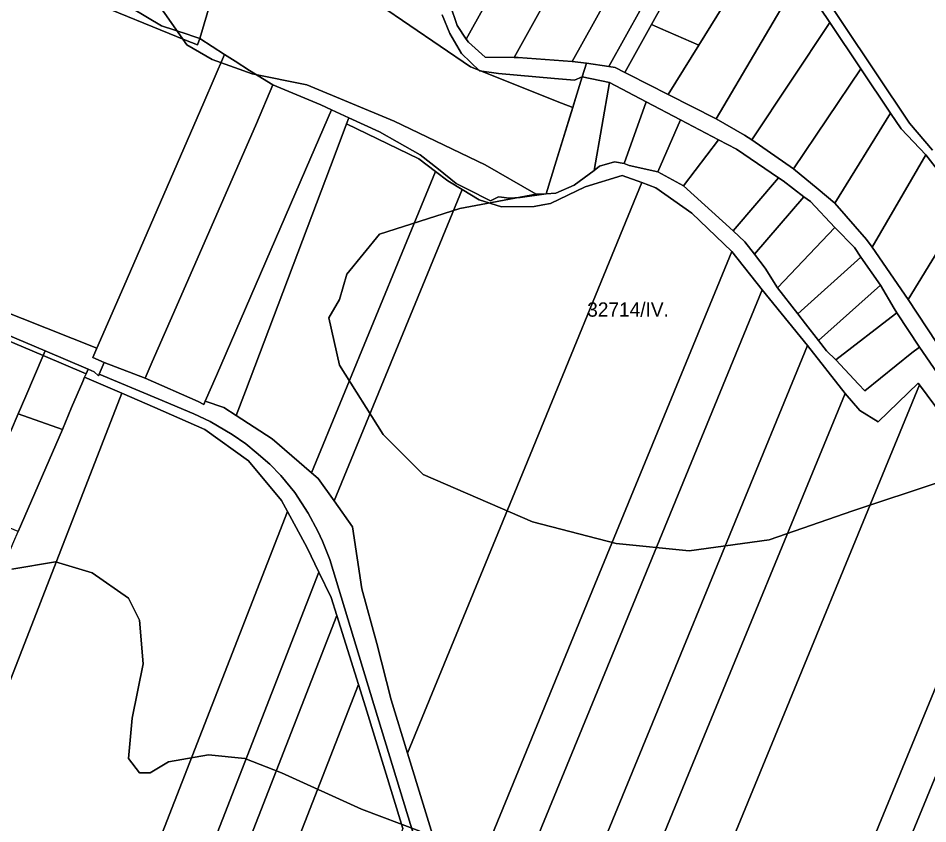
# Model space of a CAD drawing. Extents: x -545779 to -541342, y -1153413 to -1149956.
# Drawn here: x -543743 to -543424.2, y -1151725.6 to -1151443.3 of the extents above; entities that cross this region are included whole.
import ezdxf

# ---------------------------------------------------------------- set-up
doc = ezdxf.new("R2010")
doc.units = 0
for name, color, linetype in [('95560013', 7, 'Continuous'), ('95590013', 7, 'Continuous'), ('95600013', 7, 'Continuous'), ('95610013', 7, 'Continuous'), ('95620013', 7, 'Continuous'), ('95640013', 7, 'Continuous'), ('95660013', 7, 'Continuous')]:
    doc.layers.add(name, color=color, linetype=linetype)

msp = doc.modelspace()

# ---------------------------------------------------------------- linework, layer by layer
at = {"layer": '95560013'}
for points in [[(-543546.06, -1151342.91), (-543543.88, -1151346.35), (-543541.07, -1151350.8), (-543534.97, -1151358.76), (-543586.01, -1151450.59), (-543589.23, -1151445.86), (-543591.62, -1151438.6), (-543594.77, -1151430.54)], [(-543534.97, -1151358.76), (-543533.65, -1151360.47), (-543532.32, -1151361.53), (-543527.78, -1151365.16), (-543521.08, -1151368.18), (-543520.12, -1151368.63), (-543569.25, -1151457.02), (-543579.35, -1151456.9), (-543585.26, -1151451.7), (-543586.01, -1151450.59)], [(-543567.82, -1151457.04), (-543569.25, -1151457.02), (-543520.12, -1151368.63), (-543516.81, -1151370.19), (-543506.27, -1151375.14), (-543503.78, -1151376.31), (-543503.48, -1151376.77), (-543548.87, -1151458.44)], [(-543543.87, -1151459.07), (-543548.87, -1151458.44), (-543503.48, -1151376.77), (-543501.28, -1151380.06), (-543495.92, -1151388.1), (-543536.02, -1151460.25)], [(-543495.92, -1151388.1), (-543493.77, -1151391.33), (-543492.25, -1151393.62), (-543521.1, -1151445.52), (-543530.42, -1151462.28), (-543533.78, -1151460.57), (-543536.02, -1151460.25)], [(-543492.25, -1151393.62), (-543479.79, -1151412.85), (-543504.52, -1151452.78), (-543517.95, -1151446.9), (-543521.1, -1151445.52)], [(-543716.83, -1151562.15), (-543715.42, -1151558.92), (-543706.06, -1151537.35), (-543678.02, -1151472.79), (-543670.71, -1151455.96), (-543667, -1151458.37), (-543661.98, -1151461.63), (-543653.77, -1151466.67), (-543659.57, -1151480.23), (-543687.7, -1151544.6), (-543696.06, -1151563.74), (-543698.58, -1151569.5), (-543712.85, -1151563.9)], [(-543653.77, -1151466.67), (-543636.94, -1151473.63), (-543633.23, -1151475.34), (-543638.97, -1151488.6), (-543666.8, -1151552.84), (-543673.57, -1151568.46), (-543677.49, -1151577.51), (-543677.98, -1151578.64), (-543679.91, -1151577.65), (-543698.58, -1151569.5), (-543696.06, -1151563.74), (-543687.7, -1151544.6), (-543659.57, -1151480.23)], [(-543631.94, -1151490.93), (-543627.92, -1151480.3), (-543602.67, -1151492.57), (-543596.78, -1151496.97), (-543640.19, -1151602.62), (-543653.99, -1151590.76), (-543666.67, -1151582.48), (-543663.37, -1151574.05)], [(-543640.19, -1151602.62), (-543596.78, -1151496.97), (-543592.42, -1151500.23), (-543587.43, -1151503.28), (-543632.3, -1151612.47), (-543637.86, -1151604.63)], [(-543581.5, -1151506.9), (-543573.6, -1151509.37), (-543562.19, -1151509.28), (-543559.14, -1151508.73), (-543556.44, -1151508.25), (-543544.32, -1151502.42), (-543531.31, -1151498.38), (-543524.44, -1151500.91), (-543565.52, -1151600.89), (-543606.61, -1151700.87), (-543612.37, -1151682.17), (-543617.34, -1151662.42), (-543622.57, -1151643.32), (-543625.86, -1151621.57), (-543632.3, -1151612.47), (-543587.43, -1151503.28)], [(-543540.88, -1151641.8), (-543588.85, -1151758.53), (-543589.15, -1151757.56), (-543606.61, -1151700.87), (-543565.52, -1151600.89), (-543524.44, -1151500.91), (-543519.6, -1151502.7), (-543506.97, -1151511.62), (-543492.9, -1151525.06)], [(-543482.25, -1151538.53), (-543532.06, -1151659.72), (-543581.86, -1151780.91), (-543588.85, -1151758.53), (-543540.88, -1151641.8), (-543492.9, -1151525.06)], [(-543571.54, -1151813.98), (-543581.86, -1151780.91), (-543532.06, -1151659.72), (-543482.25, -1151538.53), (-543466.34, -1151558.01), (-543518.94, -1151685.99)], [(-543466.34, -1151558.01), (-543453.25, -1151574.82), (-543508.2, -1151708.53), (-543563.15, -1151842.24), (-543563.68, -1151840.49), (-543565.94, -1151831.89), (-543571.54, -1151813.98), (-543518.94, -1151685.99)], [(-543744.51, -1151626.74), (-543743.07, -1151623.2), (-543727.55, -1151587.41), (-543724.37, -1151579.78), (-543720.4, -1151570.58), (-543719.77, -1151569.13), (-543706.77, -1151574.74), (-543749.64, -1151684.78), (-543792.5, -1151794.83), (-543808.08, -1151778.88)], [(-543552.58, -1151876.88), (-543563.15, -1151842.24), (-543508.2, -1151708.53), (-543453.25, -1151574.82), (-543448.01, -1151580.83), (-543441.65, -1151584.81), (-543427.65, -1151571.22), (-543427.2, -1151571.8), (-543489.89, -1151724.34)], [(-543418.53, -1151627.26), (-543406.97, -1151642.49), (-543468.49, -1151792.18), (-543530.01, -1151941.87), (-543533.97, -1151930.97), (-543541.88, -1151911.96), (-543552.58, -1151876.88), (-543489.89, -1151724.34), (-543427.2, -1151571.8), (-543402.91, -1151604.4)], [(-543741.95, -1151855.55), (-543762.98, -1151828.24), (-543789.76, -1151797.63), (-543792.5, -1151794.83), (-543749.64, -1151684.78), (-543706.77, -1151574.74), (-543695.14, -1151579.76), (-543677.64, -1151587.49), (-543662.32, -1151598.44), (-543650.77, -1151612.28), (-543648.69, -1151616.13), (-543695.32, -1151735.84)], [(-543695.32, -1151735.84), (-543648.69, -1151616.13), (-543641.79, -1151628.89), (-543637.69, -1151637.4), (-543683.63, -1151755.34), (-543729.57, -1151873.29), (-543738.74, -1151859.72), (-543741.95, -1151855.55)], [(-543683.63, -1151755.34), (-543637.69, -1151637.4), (-543633.38, -1151646.34), (-543631.4, -1151652.63), (-543676.61, -1151768.7), (-543721.82, -1151884.77), (-543729.57, -1151873.29)], [(-543398.65, -1151653.46), (-543461.32, -1151805.95), (-543523.99, -1151958.44), (-543530.01, -1151941.87), (-543468.49, -1151792.18), (-543406.97, -1151642.49)], [(-543631.4, -1151652.63), (-543623.77, -1151676.81), (-543667.58, -1151789.26), (-543711.38, -1151901.72), (-543718.05, -1151890.35), (-543721.82, -1151884.77), (-543676.61, -1151768.7)], [(-543521.45, -1151965.43), (-543523.99, -1151958.44), (-543461.32, -1151805.95), (-543398.65, -1151653.46), (-543390.07, -1151664.07), (-543453.49, -1151818.38), (-543516.9, -1151972.68)], [(-543667.58, -1151789.26), (-543623.77, -1151676.81), (-543621.29, -1151684.66), (-543608.23, -1151727.3), (-543649.67, -1151833.67), (-543691.1, -1151940.05), (-543695.44, -1151928.88), (-543711.38, -1151901.72)]]:
    msp.add_lwpolyline(points, close=True, dxfattribs=at)
at = {"layer": '95590013'}
for points in [[(-543535.82, -1151465.83), (-543523, -1151472.57), (-543530.69, -1151494.15), (-543533.99, -1151493.66), (-543539.32, -1151495.16), (-543541.15, -1151496.63)], [(-543467.08, -1151550.37), (-543469.84, -1151546.86), (-543447.68, -1151526.99), (-543440.86, -1151536.84), (-543462.57, -1151556.23)], [(-543727.55, -1151587.41), (-543743.07, -1151623.2), (-543748.63, -1151620.84), (-543750.15, -1151624.4), (-543759.65, -1151620.27), (-543745.77, -1151588.28), (-543743.01, -1151581.92)]]:
    msp.add_lwpolyline(points, close=True, dxfattribs=at)
at = {"layer": '95600013'}
msp.add_lwpolyline([(-543664.49, -1151393.61), (-543660.7, -1151397.48), (-543661.86, -1151400.51), (-543663.64, -1151405.14), (-543664.82, -1151408.21), (-543673.88, -1151431.71), (-543679.37, -1151450.34), (-543682.23, -1151449.41), (-543683.51, -1151448.99), (-543692.85, -1151445.93), (-543769.18, -1151400.33), (-543759.62, -1151391.46), (-543753.2, -1151381.33), (-543752.52, -1151379.28), (-543751.06, -1151374.9), (-543743.07, -1151354.05), (-543739.44, -1151355.73), (-543677.42, -1151384.4), (-543669.09, -1151388.9), (-543668.09, -1151389.92), (-543664.86, -1151393.23)], close=True, dxfattribs=at)
at = {"layer": '95610013'}
msp.add_lwpolyline([(-543594.46, -1151442.1), (-543591.78, -1151448.59), (-543587.72, -1151455.68), (-543581.39, -1151461.78), (-543574.68, -1151462.7), (-543555.06, -1151464.37), (-543548.05, -1151464.97), (-543545.33, -1151463.81), (-543547.19, -1151469.85), (-543554.44, -1151493.44), (-543557.95, -1151504.85), (-543567.07, -1151506.11), (-543570.98, -1151506.41), (-543573.65, -1151506), (-543574.71, -1151505.84), (-543577.47, -1151507.34), (-543585.58, -1151503.18), (-543589.52, -1151501.16), (-543595.75, -1151496.21), (-543602.15, -1151491.12), (-543610.18, -1151486.59), (-543616.45, -1151483.05), (-543627.11, -1151478.15), (-543633.23, -1151475.34), (-543636.94, -1151473.63), (-543653.77, -1151466.67), (-543661.98, -1151461.63), (-543667, -1151458.37), (-543670.71, -1151455.96), (-543679.37, -1151450.34), (-543673.88, -1151431.71)], dxfattribs=at)
at = {"layer": '95620013'}
for points in [[(-543504.52, -1151452.78), (-543479.79, -1151412.85), (-543469.2, -1151428.92), (-543498.42, -1151478.56), (-543515.19, -1151470.03)], [(-543488.42, -1151484.25), (-543498.42, -1151478.56), (-543469.2, -1151428.92), (-543458.58, -1151444.8), (-543485.9, -1151485.95)], [(-543471.36, -1151496.06), (-543485.9, -1151485.95), (-543458.58, -1151444.8), (-543447.74, -1151461.02)], [(-543437.25, -1151476.51), (-543456.8, -1151508.08), (-543462.64, -1151503.2), (-543471.36, -1151496.06), (-543447.74, -1151461.02)], [(-543547.19, -1151469.85), (-543545.33, -1151463.81), (-543535.82, -1151465.83), (-543541.15, -1151496.63), (-543548.12, -1151501.85), (-543554.56, -1151504.63), (-543557.95, -1151504.85), (-543554.44, -1151493.44)], [(-543523, -1151472.57), (-543510.87, -1151478.85), (-543518.86, -1151497.08), (-543528.85, -1151494.87), (-543530.69, -1151494.15)], [(-543424.88, -1151491.22), (-543443.74, -1151523.48), (-543445.7, -1151520.79), (-543456.8, -1151508.08), (-543437.25, -1151476.51), (-543433.59, -1151482.06)], [(-543509.82, -1151502.08), (-543518.86, -1151497.08), (-543510.87, -1151478.85), (-543497.58, -1151485.86)], [(-543476.52, -1151499.2), (-543492.49, -1151517.83), (-543509.82, -1151502.08), (-543497.58, -1151485.86), (-543491.26, -1151489.17)], [(-543431.06, -1151541.91), (-543443.74, -1151523.48), (-543424.88, -1151491.22), (-543411.05, -1151509.1)], [(-543474.92, -1151500.33), (-543467.66, -1151505.9), (-543485.01, -1151526.02), (-543488.39, -1151521.61), (-543492.49, -1151517.83), (-543476.52, -1151499.2)], [(-543456.83, -1151516.63), (-543476.86, -1151537.75), (-543481.27, -1151530.84), (-543485.01, -1151526.02), (-543467.66, -1151505.9), (-543465.35, -1151507.53)], [(-543396.33, -1151528.09), (-543417.85, -1151562.13), (-543431.06, -1151541.91), (-543411.05, -1151509.1)], [(-543469.84, -1151546.86), (-543476.86, -1151537.75), (-543456.83, -1151516.63), (-543449.88, -1151523.61), (-543447.68, -1151526.99)], [(-543459.71, -1151559.9), (-543462.57, -1151556.23), (-543440.86, -1151536.84), (-543436.03, -1151545.04), (-543435.05, -1151546.56), (-543435.56, -1151546.95), (-543456.44, -1151563.03)], [(-543448.56, -1151571.58), (-543456.44, -1151563.03), (-543435.56, -1151546.95), (-543435.05, -1151546.56), (-543427.14, -1151558.55), (-543429.78, -1151560.61), (-543446.29, -1151573.93)]]:
    msp.add_lwpolyline(points, close=True, dxfattribs=at)
at = {"layer": '95640013'}
for points in [[(-543743.38, -1151424.94), (-543769.18, -1151400.33), (-543692.85, -1151445.93), (-543683.51, -1151448.99), (-543682.23, -1151449.41), (-543679.37, -1151450.34), (-543680.2, -1151452.67), (-543684.44, -1151450.94), (-543719.33, -1151436.66)], [(-543757.53, -1151453.69), (-543745.24, -1151428.52), (-543721.15, -1151440.34), (-543719.33, -1151436.66), (-543684.44, -1151450.94), (-543680.2, -1151452.67), (-543679.37, -1151450.34), (-543670.71, -1151455.96), (-543678.02, -1151472.79), (-543706.06, -1151537.35), (-543715.42, -1151558.92), (-543794.09, -1151527.78), (-543788.93, -1151517.51)], [(-543504.52, -1151452.78), (-543515.19, -1151470.03), (-543529.02, -1151462.99), (-543530.42, -1151462.28), (-543521.1, -1151445.52), (-543517.95, -1151446.9)], [(-543673.57, -1151568.46), (-543666.8, -1151552.84), (-543638.97, -1151488.6), (-543633.23, -1151475.34), (-543627.11, -1151478.15), (-543627.92, -1151480.3), (-543631.94, -1151490.93), (-543663.37, -1151574.05), (-543666.67, -1151582.48), (-543670.94, -1151579.7), (-543677.49, -1151577.51)], [(-543747.32, -1151554.02), (-543733.57, -1151559.9), (-543734.26, -1151561.53), (-543748.02, -1151555.68)], [(-543749.15, -1151558.37), (-543748.02, -1151555.68), (-543734.26, -1151561.53), (-543740.33, -1151575.78), (-543743.01, -1151581.92), (-543745.77, -1151588.28), (-543755.05, -1151584.3), (-543756.84, -1151588.38), (-543761.39, -1151586.15), (-543759.74, -1151582.27), (-543757.47, -1151577.54), (-543756.7, -1151575.34), (-543754.25, -1151569.93), (-543753.38, -1151567.96)], [(-543718.55, -1151566.32), (-543719.24, -1151567.9), (-543734.26, -1151561.53), (-543733.57, -1151559.9)], [(-543734.26, -1151561.53), (-543719.24, -1151567.9), (-543719.77, -1151569.13), (-543720.4, -1151570.58), (-543724.37, -1151579.78), (-543727.55, -1151587.41), (-543743.01, -1151581.92), (-543740.33, -1151575.78)]]:
    msp.add_lwpolyline(points, close=True, dxfattribs=at)
for points in [[(-543411.05, -1151509.1), (-543424.88, -1151491.22), (-543433.59, -1151482.06), (-543437.25, -1151476.51), (-543447.74, -1151461.02), (-543458.58, -1151444.8), (-543469.2, -1151428.92)], [(-543466.03, -1151427.04), (-543430.64, -1151480.07), (-543422.57, -1151489.55)], [(-543422.57, -1151489.55), (-543430.64, -1151480.07), (-543466.03, -1151427.04)], [(-543591.62, -1151438.6), (-543589.23, -1151445.86), (-543586.01, -1151450.59), (-543585.26, -1151451.7), (-543579.35, -1151456.9), (-543569.25, -1151457.02), (-543567.82, -1151457.04), (-543548.87, -1151458.44), (-543543.87, -1151459.07), (-543536.02, -1151460.25), (-543533.78, -1151460.57), (-543530.42, -1151462.28), (-543529.02, -1151462.99), (-543515.19, -1151470.03), (-543498.42, -1151478.56), (-543488.42, -1151484.25), (-543485.9, -1151485.95), (-543471.36, -1151496.06), (-543462.64, -1151503.2), (-543456.8, -1151508.08), (-543445.7, -1151520.79), (-543443.74, -1151523.48), (-543431.06, -1151541.91), (-543417.85, -1151562.13)], [(-543418.36, -1151571.3), (-543427.14, -1151558.55), (-543435.05, -1151546.56), (-543436.03, -1151545.04), (-543440.86, -1151536.84), (-543447.68, -1151526.99), (-543449.88, -1151523.61), (-543456.83, -1151516.63), (-543465.35, -1151507.53), (-543467.66, -1151505.9), (-543474.92, -1151500.33), (-543476.52, -1151499.2), (-543491.26, -1151489.17), (-543497.58, -1151485.86), (-543510.87, -1151478.85), (-543523, -1151472.57), (-543535.82, -1151465.83), (-543545.33, -1151463.81), (-543548.05, -1151464.97), (-543555.06, -1151464.37), (-543574.68, -1151462.7), (-543581.39, -1151461.78), (-543587.72, -1151455.68), (-543591.78, -1151448.59), (-543594.46, -1151442.1)], [(-543402.91, -1151604.4), (-543427.2, -1151571.8), (-543427.65, -1151571.22), (-543441.65, -1151584.81), (-543448.01, -1151580.83), (-543453.25, -1151574.82), (-543466.34, -1151558.01), (-543482.25, -1151538.53), (-543492.9, -1151525.06), (-543506.97, -1151511.62), (-543519.6, -1151502.7), (-543524.44, -1151500.91), (-543531.31, -1151498.38), (-543544.32, -1151502.42), (-543556.44, -1151508.25), (-543559.14, -1151508.73), (-543562.19, -1151509.28), (-543573.6, -1151509.37), (-543581.5, -1151506.9), (-543587.43, -1151503.28), (-543592.42, -1151500.23), (-543596.78, -1151496.97), (-543602.67, -1151492.57), (-543627.92, -1151480.3), (-543627.11, -1151478.15), (-543616.45, -1151483.05), (-543610.18, -1151486.59), (-543602.15, -1151491.12), (-543595.75, -1151496.21), (-543589.52, -1151501.16), (-543585.58, -1151503.18), (-543577.47, -1151507.34), (-543574.71, -1151505.84), (-543573.65, -1151506), (-543570.98, -1151506.41), (-543567.07, -1151506.11), (-543557.95, -1151504.85), (-543554.56, -1151504.63), (-543548.12, -1151501.85), (-543541.15, -1151496.63), (-543539.32, -1151495.16), (-543533.99, -1151493.66), (-543530.69, -1151494.15), (-543528.85, -1151494.87), (-543518.86, -1151497.08), (-543509.82, -1151502.08), (-543492.49, -1151517.83), (-543488.39, -1151521.61), (-543485.01, -1151526.02), (-543481.27, -1151530.84), (-543476.86, -1151537.75), (-543469.84, -1151546.86), (-543467.08, -1151550.37), (-543462.57, -1151556.23), (-543459.71, -1151559.9), (-543456.44, -1151563.03), (-543448.56, -1151571.58), (-543446.29, -1151573.93), (-543429.78, -1151560.61), (-543427.14, -1151558.55), (-543418.36, -1151571.3)], [(-543794.09, -1151527.78), (-543715.42, -1151558.92), (-543716.83, -1151562.15), (-543712.85, -1151563.9), (-543714.66, -1151568.03), (-543714.92, -1151568.61), (-543716.37, -1151567.25), (-543718.55, -1151566.32), (-543733.57, -1151559.9), (-543747.32, -1151554.02)], [(-543592.18, -1151769.46), (-543618.43, -1151683.78), (-543633.87, -1151633.01), (-543636.34, -1151626.56), (-543638.06, -1151623.03), (-543641.36, -1151616.74), (-543646.11, -1151609.56), (-543650.94, -1151603.61), (-543654.84, -1151599.58), (-543659.67, -1151595.45), (-543663.22, -1151592.52), (-543668.08, -1151589.18), (-543675.73, -1151584.69), (-543681.44, -1151581.91), (-543693.99, -1151576.73), (-543714.66, -1151568.03), (-543712.85, -1151563.9), (-543698.58, -1151569.5), (-543679.91, -1151577.65), (-543677.98, -1151578.64), (-543677.49, -1151577.51), (-543670.94, -1151579.7), (-543666.67, -1151582.48), (-543653.99, -1151590.76), (-543640.19, -1151602.62), (-543637.86, -1151604.63), (-543632.3, -1151612.47), (-543625.86, -1151621.57), (-543622.57, -1151643.32), (-543617.34, -1151662.42), (-543612.37, -1151682.17), (-543606.61, -1151700.87), (-543589.15, -1151757.56)], [(-543608.23, -1151727.3), (-543621.29, -1151684.66), (-543623.77, -1151676.81), (-543631.4, -1151652.63), (-543633.38, -1151646.34), (-543637.69, -1151637.4), (-543641.79, -1151628.89), (-543648.69, -1151616.13), (-543650.77, -1151612.28), (-543662.32, -1151598.44), (-543677.64, -1151587.49), (-543695.14, -1151579.76), (-543706.77, -1151574.74), (-543719.77, -1151569.13), (-543719.24, -1151567.9), (-543718.55, -1151566.32), (-543716.37, -1151567.25), (-543714.92, -1151568.61), (-543714.66, -1151568.03), (-543693.99, -1151576.73), (-543681.44, -1151581.91), (-543675.73, -1151584.69), (-543668.08, -1151589.18), (-543663.22, -1151592.52), (-543659.67, -1151595.45), (-543654.84, -1151599.58), (-543650.94, -1151603.61), (-543646.11, -1151609.56), (-543641.36, -1151616.74), (-543638.06, -1151623.03), (-543636.34, -1151626.56), (-543633.87, -1151633.01), (-543618.43, -1151683.78), (-543592.18, -1151769.46)]]:
    msp.add_lwpolyline(points, dxfattribs=at)
at = {"layer": '95660013'}
msp.add_lwpolyline([(-543552.561, -1151473.03), (-543548.647, -1151474.591), (-543554.44, -1151493.44), (-543557.95, -1151504.85), (-543561.493, -1151504.929), (-543579.355, -1151494.721), (-543611.254, -1151479.409), (-543641.879, -1151466.65), (-543661.018, -1151462.822), (-543675.053, -1151457.718), (-543683.985, -1151452.614), (-543695.469, -1151436.027), (-543722.263, -1151425.819), (-543750, -1151406.8), (-543766.923, -1151395.196), (-543750, -1151362.24), (-543742.68, -1151347.985), (-543726.092, -1151354.365), (-543689.088, -1151374.78), (-543671.226, -1151383.712), (-543657.189, -1151396.472), (-543641.879, -1151415.611), (-543616.357, -1151438.578), (-543584.46, -1151460.27)], close=True, dxfattribs=at)
for points in [[(-543479.79, -1151412.85), (-543504.52, -1151452.78), (-543517.95, -1151446.9), (-543521.1, -1151445.52), (-543530.42, -1151462.28), (-543533.78, -1151460.57), (-543536.02, -1151460.25), (-543543.87, -1151459.07), (-543545.33, -1151463.81), (-543547.19, -1151469.85), (-543548.647, -1151474.591), (-543552.561, -1151473.03), (-543584.46, -1151460.27), (-543616.357, -1151438.578)], [(-543418.36, -1151571.3), (-543427.14, -1151558.55), (-543429.78, -1151560.61), (-543446.29, -1151573.93), (-543448.56, -1151571.58), (-543456.44, -1151563.03), (-543459.71, -1151559.9), (-543462.57, -1151556.23), (-543440.86, -1151536.84), (-543447.68, -1151526.99), (-543469.84, -1151546.86), (-543476.86, -1151537.75), (-543481.27, -1151530.84), (-543485.01, -1151526.02), (-543488.39, -1151521.61), (-543492.49, -1151517.83), (-543509.82, -1151502.08), (-543518.86, -1151497.08), (-543528.85, -1151494.87), (-543530.69, -1151494.15), (-543523, -1151472.57), (-543535.82, -1151465.83), (-543541.15, -1151496.63), (-543548.12, -1151501.85), (-543554.56, -1151504.63), (-543557.95, -1151504.85), (-543554.44, -1151493.44), (-543548.647, -1151474.591), (-543547.19, -1151469.85), (-543545.33, -1151463.81), (-543543.87, -1151459.07), (-543536.02, -1151460.25), (-543533.78, -1151460.57), (-543530.42, -1151462.28), (-543521.1, -1151445.52), (-543517.95, -1151446.9), (-543504.52, -1151452.78), (-543479.79, -1151412.85)], [(-543695.469, -1151436.027), (-543683.985, -1151452.614), (-543675.053, -1151457.718), (-543661.018, -1151462.822), (-543641.879, -1151466.65), (-543611.254, -1151479.409), (-543579.355, -1151494.721), (-543561.493, -1151504.929), (-543588.287, -1151510.033), (-543616.357, -1151518.964), (-543627.842, -1151533), (-543630.395, -1151541.932), (-543634.221, -1151548.312), (-543630.395, -1151564.899), (-543615.083, -1151589.143), (-543601.048, -1151603.178), (-543562.768, -1151619.766), (-543533.421, -1151627.422), (-543507.901, -1151629.973), (-543479.831, -1151626.146), (-543450.482, -1151615.938), (-543419.86, -1151605.73)], [(-543419.86, -1151605.73), (-543450.482, -1151615.938), (-543479.831, -1151626.146), (-543507.901, -1151629.973), (-543533.421, -1151627.422), (-543562.768, -1151619.766), (-543601.048, -1151603.178), (-543615.083, -1151589.143), (-543630.395, -1151564.899), (-543634.221, -1151548.312), (-543630.395, -1151541.932), (-543627.842, -1151533), (-543616.357, -1151518.964), (-543588.287, -1151510.033), (-543561.493, -1151504.929), (-543557.95, -1151504.85), (-543554.56, -1151504.63), (-543548.12, -1151501.85), (-543541.15, -1151496.63), (-543535.82, -1151465.83), (-543523, -1151472.57), (-543530.69, -1151494.15), (-543528.85, -1151494.87), (-543518.86, -1151497.08), (-543509.82, -1151502.08), (-543492.49, -1151517.83), (-543488.39, -1151521.61), (-543485.01, -1151526.02), (-543481.27, -1151530.84), (-543476.86, -1151537.75), (-543469.84, -1151546.86), (-543447.68, -1151526.99), (-543440.86, -1151536.84), (-543462.57, -1151556.23), (-543459.71, -1151559.9), (-543456.44, -1151563.03), (-543448.56, -1151571.58), (-543446.29, -1151573.93), (-543429.78, -1151560.61), (-543427.14, -1151558.55), (-543418.36, -1151571.3)], [(-543745.232, -1151636.353), (-543729.919, -1151633.801), (-543717.16, -1151637.629), (-543704.401, -1151646.561), (-543700.572, -1151654.217), (-543699.296, -1151669.528), (-543703.125, -1151688.668), (-543704.401, -1151702.704), (-543700.572, -1151707.807), (-543696.745, -1151707.807), (-543690.364, -1151703.98), (-543676.329, -1151701.428), (-543663.57, -1151702.704), (-543650.809, -1151707.807), (-543622.739, -1151720.567), (-543602.322, -1151728.223)], [(-543602.322, -1151728.223), (-543622.739, -1151720.567), (-543650.809, -1151707.807), (-543663.57, -1151702.704), (-543676.329, -1151701.428), (-543690.364, -1151703.98), (-543696.745, -1151707.807), (-543700.572, -1151707.807), (-543704.401, -1151702.704), (-543703.125, -1151688.668), (-543699.296, -1151669.528), (-543700.572, -1151654.217), (-543704.401, -1151646.561), (-543717.16, -1151637.629), (-543729.919, -1151633.801), (-543745.232, -1151636.353)]]:
    msp.add_lwpolyline(points, dxfattribs=at)

# ---------------------------------------------------------------- texts
msp.add_text('32714/IV.', height=5, rotation=360, dxfattribs=at).set_placement((-543543.61, -1151547.901))

doc.saveas('drawing.dxf')
